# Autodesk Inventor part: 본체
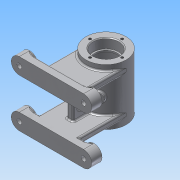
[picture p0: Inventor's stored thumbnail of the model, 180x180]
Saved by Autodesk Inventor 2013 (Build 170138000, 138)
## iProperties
Created: 2015-11
Part Number: 본체
Material: 알루미늄 6061
Document SubType Name: Modeling
Designer: Administrator
Density: 2.71 g/cm^3
Mass: 358.456 g
Surface Area: 463.793 cm^2
Volume: 132.272 cm^3
Author: Administrator
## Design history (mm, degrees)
sketch "스케치1"
  geometry: C1 r 25 at (0, 0); 1 further point
  constraints: 1 centre point, 1 coincident
  dimensions: "d0" = 50 diameter of C1
extrude "돌출1" new body sketch "스케치1" stored distance "d1" = 70; taper "d2" = 0 deg
hole "구멍1" diameter "d5" = 28; stored, may be unused: countersink angle "d9" = 90 deg, drill point angle "d11" = 0 deg; dims "d3" = 10, "d4" = 10, "d6" = 6, "d7" = 32, "d8" = 12, "d10" = 35
sketch "스케치2"
  geometry: C1 r 16 at (0, 0) reference; 1 further point
  constraints: 1 vertical alignment
  dimensions: "d12" = 20 distance of C1.centre point (0, 20)
hole "구멍2" sketch "스케치2" at (0, 20) diameter "d13" = 3.242; stored, may be unused: countersink angle "d17" = 90 deg, drill point angle "d19" = 118 deg; dims "d14" = 8, "d15" = 32, "d16" = 12, "d18" = 10
sketch "스케치3"
  geometry: C1 r 21 at (0, 0); 1 further point
  constraints: 1 centre point, 1 coincident
  dimensions: "d23" = 42 diameter of C1
extrude "돌출2" cut sketch "스케치3" stored distance "d24" = 42; taper "d25" = 0 deg
sketch "스케치4"
  geometry: L1 (0, 0)-(14, -24.249); L2 (0, 0)-(28, 0)
  constraints: 4 end point, 1 equal length, 1 horizontal
  dimensions: "d26" = 28 distance of L1.start L1.end; "d27" = 60 deg angle of L1 L2
node "작업 평면1"
sketch "스케치5"
  geometry: C1 r 6 at (0, 0); 1 further point
  constraints: 1 centre point, 1 coincident
  dimensions: "d28" = 12 diameter of C1
extrude "돌출3" join sketch "스케치5" stored distance "d29" = 42; taper "d30" = 0 deg
hole "구멍3" diameter "d33" = 5.188; stored, may be unused: countersink angle "d37" = 90 deg, drill point angle "d39" = 118 deg; dims "d31" = 10, "d32" = 10, "d34" = 8, "d35" = 32, "d36" = 12, "d38" = 10
node "작업 평면2"
sketch "스케치6"
  geometry: L1 (-40, -20)-(40, -20); L2 (-40, -40)-(40, -40); A1 r 10 centre (-40, -30) between (-40, -20) and (-40, -40); A2 r 10 centre (40, -30) between (40, -20) and (40, -40); 2 further points
  constraints: 4 end point, 4 point on circle, 4 tangent, 2 centre point, 1 horizontal alignment, 1 midpoint, 1 vertical alignment
  dimensions: "d41" = 20 diameter of A1; "d42" = 20 diameter of A2; "d43" = 80 distance of A2.centre A1.centre; "d44" = 40 distance from line of point (0, 0) L2
extrude "돌출4" join sketch "스케치6" distance "d45" = 13; taper "d46" = 0 deg
extrude "돌출5" join sketch "스케치6" distance "d47" = 10; taper "d48" = 0 deg
hole "구멍4" diameter "d51" = 6; stored, may be unused: countersink angle "d55" = 90 deg, drill point angle "d57" = 0 deg; dims "d49" = 10, "d50" = 10, "d52" = 8, "d53" = 12, "d54" = 4, "d56" = 10
hole "구멍5" diameter "d60" = 6; stored, may be unused: countersink angle "d64" = 90 deg, drill point angle "d66" = 0 deg; dims "d58" = 10, "d59" = 10, "d61" = 8, "d62" = 12, "d63" = 4, "d65" = 10
sketch "스케치7"
  geometry: L1 (-40, 20)-(40, 20) reference; L2 (-25, 28)-(25, 28); L3 (25, 28)-(25, 20); L4 (25, 20)-(-25, 20); L5 (-25, 20)-(-25, 28); 2 further points
  constraints: 8 end point, 2 midpoint, 2 parallel, 1 horizontal, 1 perpendicular
  dimensions: "d67" = 50 distance of L3.end L4.end; "d68" = 8 distance of L2.end L3.end
extrude "돌출6" join sketch "스케치7" stored distance "d69" = 10; taper "d70" = 0 deg
node "작업 평면3"
sketch "스케치8"
  geometry: L1 (25, 28)-(25, 20) reference; L2 (25, 20)-(-25, 20) reference; L3 (-25, 20)-(-25, 28) reference; L4 (-25, 28)-(25, 28) reference; L5 (25, -20)-(25, -28) reference; L6 (25, -28)-(-25, -28) reference; L7 (-25, -28)-(-25, -20) reference; L8 (-25, -20)-(25, -20) reference; L9 (-4, 20)-(-4, -20); L10 (4, 20)-(4, -20); 1 further point
  constraints: 4 end point, 4 point on line, 2 perpendicular
  dimensions: "d72" = 4 distance from line of point (0, 0) L9; "d73" = 8 distance between parallel lines of L10 L9
extrude "돌출7" join sketch "스케치8" stored distance "d74" = 10; taper "d75" = 0 deg
sketch "스케치9"
  geometry: L1 (8.5, 13.5)-(31.5, 13.5); L2 (31.5, 13.5)-(31.5, 6.5); L3 (31.5, 6.5)-(8.5, 6.5); L4 (8.5, 6.5)-(8.5, 13.5); L5 (40, -23)-(60, -23) reference; 1 further point
  constraints: 8 end point, 2 parallel, 1 horizontal, 1 perpendicular
  dimensions: "d76" = 23 distance of L2.end L3.end; "d77" = 7 distance of L1.end L2.end; "d78" = 11.5 distance from line of point (20, 45) L4; "d79" = 36.5 distance between parallel lines of L5 L1
extrude "돌출8" cut sketch "스케치9" stored distance "d80" = 10; taper "d81" = 0 deg
fillet "모깎기1" dims "d82" = 3.5
node "작업 평면4"
sketch "스케치10"
  geometry: C1 r 5 at (-40, -40); 1 further point
  constraints: 1 centre point, 1 coincident
  dimensions: "d84" = 10 diameter of C1
extrude "돌출9" join sketch "스케치10" stored distance "d85" = 10; taper "d86" = 0 deg
hole "구멍6" diameter "d89" = 5.188; stored, may be unused: countersink angle "d93" = 90 deg, drill point angle "d95" = 0 deg; dims "d87" = 10, "d88" = 10, "d90" = 8, "d91" = 12, "d92" = 4, "d94" = 10
fillet "모깎기2" dims "d96" = 0.3
chamfer "모따기1" distance "d97" = 1; stored, may be unused: second distance "d98" = 2, angle "d99" = 45 deg
fillet "모깎기3" dims "d100" = 2
fillet "모깎기5" dims "d102" = 3
node "작업 평면5"
sketch "스케치11"
  geometry: 2 further points
  constraints: 1 coincident, 1 other
feature "엠보싱1" sketch "스케치11" dims "d103" = 0.5, "d104" = 0
fillet "모깎기6" dims "d105" = 2
fillet "모깎기7" dims "d106" = 2
fillet "모깎기8" dims "d107" = 2
fillet "모깎기9" dims "d108" = 2
fillet "모깎기10" dims "d109" = 2
fillet "모깎기11" dims "d110" = 0.3
chamfer "모따기2" distance "d111" = 1; stored, may be unused: second distance "d112" = 2, angle "d113" = 45 deg
node "솔리드1"
pattern_circular "원형 패턴1" dims angle "d21" = 360 deg
mirror "대칭1"
mirror "대칭2"
node "절단 모서리 투영1"
other parameters: "d40" = -68, "d71" = -45, "d83" = -96
